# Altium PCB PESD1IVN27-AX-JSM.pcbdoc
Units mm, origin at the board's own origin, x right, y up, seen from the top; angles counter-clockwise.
Board outline 15.74 x 14.15 mm, 2 copper layers (Top Layer, Bottom Layer), stack 0 mm thick; 1 components, 0 nets, 2 pads, 0 vias.
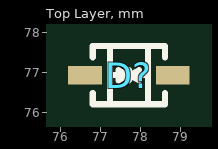
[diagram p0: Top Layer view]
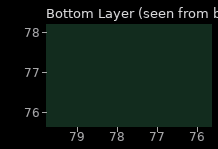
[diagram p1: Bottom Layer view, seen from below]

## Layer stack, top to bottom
Top Layer: signal copper (thickness not stored)
Bottom Layer: signal copper (thickness not stored)

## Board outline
85.59,69.85 69.85,69.85 69.85,84.002 85.59,84.002

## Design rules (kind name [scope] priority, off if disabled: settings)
PasteMaskExpansion "Paste Mask Expansion" [All] p1: expansion=0
SolderMaskExpansion "Solder Mask Expansion" [IsVia] p1: expansion=-25.4 istentingtop=TRUE
SolderMaskExpansion "Solder Mask Expansion" [All] p2: expansion=0.051 istentingtop=FALSE

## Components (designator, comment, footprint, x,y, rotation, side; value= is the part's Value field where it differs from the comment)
D? "PESD1IVN27-AX-JSM" SOD-323_L1.7-W1.3-LS2.7-BI 77.72,76.926 r0 top

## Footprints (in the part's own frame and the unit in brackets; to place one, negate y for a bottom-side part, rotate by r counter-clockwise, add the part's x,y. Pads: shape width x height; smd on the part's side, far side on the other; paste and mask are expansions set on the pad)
SOD-323_L1.7-W1.3-LS2.7-BI [mm]
  rect 0.845x0.455 smd: 1(-1.098,0) 2(1.098,0)
  silkscreen extent -0.9,-0.73 0.9,0.73

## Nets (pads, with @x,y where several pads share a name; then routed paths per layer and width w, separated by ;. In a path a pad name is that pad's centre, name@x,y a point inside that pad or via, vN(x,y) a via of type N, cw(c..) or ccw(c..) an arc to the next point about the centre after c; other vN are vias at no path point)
pads on no net: D?.1 D?.2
